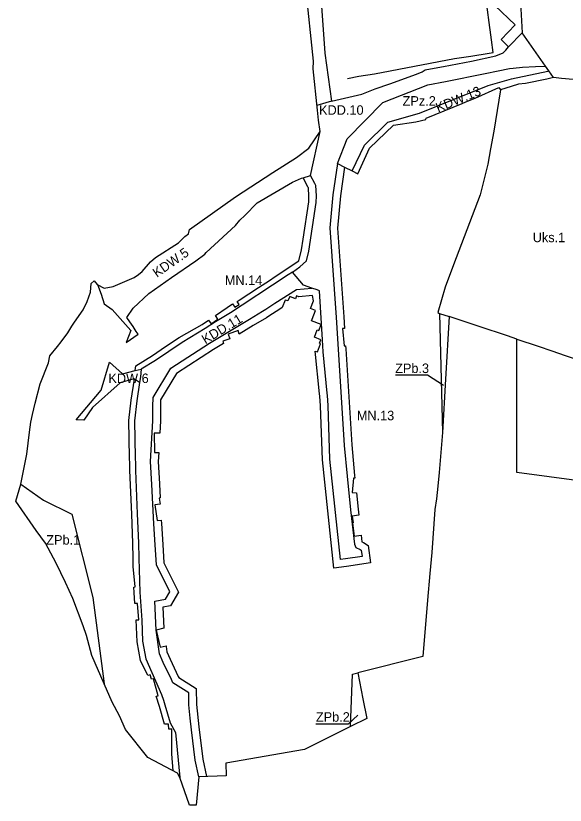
# Model space of a CAD drawing. Extents: x 7416797 to 7419013, y 5549660 to 5551534.
# Drawn here: x 7417073.2 to 7417362.3, y 5550025.1 to 5550440.3 of the extents above; entities that cross this region are included whole.
import ezdxf

# ---------------------------------------------------------------- set-up
doc = ezdxf.new("R2010")
doc.units = 0
for name, color, linetype in [('LIN_Linia Zabudowy Nieprzekraczalna', 7, 'Continuous'), ('LIN_linie_rozgraniczajace', 7, 'Continuous'), ('TXT_Oznaczenia_przeznaczen', 7, 'Continuous')]:
    doc.layers.add(name, color=color, linetype=linetype)

msp = doc.modelspace()

# ---------------------------------------------------------------- linework, layer by layer
at = {"layer": 'LIN_Linia Zabudowy Nieprzekraczalna'}
for points in [[(7417247.75, 5550407.37), (7417253.8, 5550408.44), (7417261.96, 5550409.76), (7417304.01, 5550417.81), (7417312.68, 5550419.07), (7417322.33, 5550420.71), (7417324.39, 5550421.04), (7417323.56, 5550427.64), (7417321.99, 5550439.43), (7417321.8, 5550440.84), (7417319.15, 5550460.7), (7417310.86, 5550470.5), (7417297.14, 5550487.32), (7417222.5, 5550577.57)], [(7417246.22, 5550360.69), (7417244.04, 5550345.66), (7417242.48, 5550328.66), (7417245.86, 5550281.92), (7417246.2, 5550275.84), (7417245.19, 5550275.76), (7417245.92, 5550266.61), (7417246.73, 5550266.68), (7417246.82, 5550265.17), (7417250.07, 5550214.57), (7417251.49, 5550198.49), (7417251.63, 5550197.06), (7417250.85, 5550197.11), (7417250.29, 5550189.57), (7417252.45, 5550189.39), (7417253.35, 5550180.78), (7417253.7, 5550177.66), (7417250.29, 5550177.07), (7417250.79, 5550173.66), (7417250.34, 5550173.6), (7417251.26, 5550166.59), (7417254.88, 5550167.19), (7417255.31, 5550163.58), (7417256.18, 5550163.2), (7417258.7, 5550161.72), (7417259.89, 5550152.58), (7417247.25, 5550150.7), (7417240.53, 5550149.72), (7417234.53, 5550206.76), (7417233.56, 5550235.14), (7417233.19, 5550240.22), (7417233.06, 5550241.43), (7417230.83, 5550263.92), (7417232.02, 5550263.48), (7417233.6, 5550267.82), (7417233.07, 5550268.07), (7417233.77, 5550269.92), (7417230.45, 5550271.2), (7417231.86, 5550275.07), (7417232.62, 5550274.76), (7417233.88, 5550277.84), (7417228.87, 5550279.8), (7417229.23, 5550280.74), (7417230.93, 5550285.35), (7417228.28, 5550286.37), (7417229.79, 5550290.41), (7417229.39, 5550293.12), (7417222.21, 5550292.41), (7417220.92, 5550292.92), (7417220.39, 5550291.47), (7417217.37, 5550292.57), (7417216.42, 5550290.29), (7417214.99, 5550290.79), (7417213.39, 5550286.81), (7417211.63, 5550285.69), (7417206.89, 5550282.58), (7417205.11, 5550281.48), (7417198.17, 5550277.37), (7417190.74, 5550272.9), (7417190.19, 5550274.69), (7417184.9, 5550272.8), (7417185.76, 5550270.34), (7417182.08, 5550269.11), (7417182.44, 5550267.9), (7417177.19, 5550264.75), (7417157.76, 5550252.08), (7417149.45, 5550238.3), (7417149.38, 5550234.69), (7417149.34, 5550232.65), (7417149.33, 5550227.2), (7417148.98, 5550220.68), (7417145.98, 5550220.69), (7417146.18, 5550210.55), (7417148.43, 5550210.57), (7417148.17, 5550205.77), (7417148.81, 5550194.16), (7417148.81, 5550193.96), (7417149.18, 5550186.7), (7417148.66, 5550186.62), (7417149.12, 5550183.4), (7417146.45, 5550183.1), (7417147.6, 5550174.79), (7417149.77, 5550175.07)], [(7417222.1, 5550311.42), (7417223.54, 5550317.23), (7417224.38, 5550322.78), (7417227.36, 5550342.44), (7417227.49, 5550345.47), (7417227.24, 5550349.72), (7417227.06, 5550349.99), (7417224.43, 5550355.11)], [(7417136.12, 5550253.72), (7417136.33, 5550256.25), (7417145.14, 5550261.56), (7417152.07, 5550266.3), (7417159.13, 5550271.11), (7417171.29, 5550277.95), (7417174.71, 5550280.24), (7417175.98, 5550278.34), (7417179.61, 5550280.78), (7417178.34, 5550282.67), (7417184.51, 5550286.81), (7417187.26, 5550288.78), (7417188.43, 5550286.94), (7417190.82, 5550288.46), (7417189.78, 5550290.08), (7417190.77, 5550290.71), (7417200.94, 5550297.43), (7417206.71, 5550301.14), (7417209.68, 5550303.12), (7417222.1, 5550311.42)], [(7417156, 5550043.16), (7417155.29, 5550052.07), (7417155.36, 5550065.12), (7417153.75, 5550065.09), (7417153.65, 5550067.74), (7417151.49, 5550067.68), (7417148.89, 5550077.06), (7417147.07, 5550082.35), (7417148.09, 5550082.62), (7417145.71, 5550091.56), (7417144.69, 5550091.28), (7417144.01, 5550093.69), (7417142.74, 5550093.31), (7417138.78, 5550101.2), (7417137.02, 5550111.03), (7417136.49, 5550122.54), (7417137.95, 5550122.62), (7417137.34, 5550131.24), (7417135.93, 5550131.14), (7417135.45, 5550136.89), (7417135.37, 5550139.83), (7417136.12, 5550139.91), (7417134.92, 5550150.71), (7417134.96, 5550154.93), (7417134.81, 5550162.92), (7417134.21, 5550178.14), (7417133.24, 5550201.1), (7417133.22, 5550204.45), (7417133.07, 5550207.93), (7417132.76, 5550227.34), (7417133.97, 5550238.13), (7417135.63, 5550249.12)], [(7417149.77, 5550175.07), (7417149.86, 5550173.23), (7417150.56, 5550162.21), (7417151.14, 5550152.5), (7417158.79, 5550137.12), (7417154.6, 5550129.95), (7417150.51, 5550129.15), (7417151.12, 5550118.17), (7417147, 5550117.15), (7417149.26, 5550108.2), (7417152.27, 5550108.97), (7417152.32, 5550108.61), (7417152.7, 5550105.77), (7417154.4, 5550101.84), (7417158.68, 5550092.84), (7417158.95, 5550092.28)], [(7417158.95, 5550092.28), (7417168.15, 5550086.46), (7417168.32, 5550078.1), (7417169.45, 5550066.24), (7417171.6, 5550049.37), (7417173.58, 5550040.2)]]:
    msp.add_lwpolyline(points, dxfattribs=at)
at = {"layer": 'LIN_linie_rozgraniczajace'}
for p, q in [((7417332.42, 5550424.03), (7417339.72, 5550431.23)), ((7417239.29, 5550395.46), (7417231.66, 5550393.13)), ((7417296.14, 5550283.77), (7417297.76, 5550221.07))]:
    msp.add_line(p, q, dxfattribs=at)
for points in [[(7417192.07, 5550542.59), (7417215.52, 5550524.38), (7417226.02, 5550511.19), (7417227.34, 5550506.79), (7417228.19, 5550503.17), (7417226.59, 5550485.84), (7417226.54, 5550483.39), (7417227.53, 5550475.07), (7417228.5, 5550472.11), (7417230.95, 5550473.36), (7417232.07, 5550469.35), (7417229.43, 5550467.65), (7417233.13, 5550457.84), (7417235.85, 5550420.62), (7417239.29, 5550395.46)], [(7417326.46, 5550467.59), (7417325.31, 5550460.13), (7417326.01, 5550460.16), (7417325.83, 5550454.74), (7417325.27, 5550453.92), (7417325.23, 5550445.71), (7417335.92, 5550435.5), (7417328.63, 5550427.84), (7417332.42, 5550424.03)], [(7417326.46, 5550467.59), (7417328.63, 5550465.05), (7417335.93, 5550455.83), (7417338.71, 5550447.06), (7417339.72, 5550431.23)], [(7417390.48, 5550192.96), (7417336.94, 5550200.05), (7417336.94, 5550270.27), (7417331.92, 5550271.93), (7417317.1, 5550276.78), (7417301.18, 5550282.09), (7417299.33, 5550249.13), (7417297.76, 5550221.07), (7417296.01, 5550199.99), (7417295.28, 5550192.83), (7417294.66, 5550186.18), (7417293.71, 5550180.54), (7417292.06, 5550157.96), (7417291.12, 5550147.03), (7417289.91, 5550132.95), (7417287.42, 5550103.21), (7417253.22, 5550094.63), (7417253.22, 5550094.63), (7417255.88, 5550081.06), (7417257.96, 5550070.68), (7417249.41, 5550066.42), (7417225.06, 5550054.3), (7417183.72, 5550047.24), (7417183.92, 5550040.58), (7417169.53, 5550040.05), (7417168.2, 5550025.1), (7417164.63, 5550025.07), (7417159.58, 5550039.59), (7417158.34, 5550041.93), (7417142.67, 5550050.15), (7417130.98, 5550064.94), (7417127.85, 5550072.02), (7417123.85, 5550079.26), (7417119.8, 5550088.9), (7417113.19, 5550103.9), (7417110.37, 5550114.34), (7417108.61, 5550119.37), (7417103.27, 5550133.87), (7417099.38, 5550142.22), (7417094.51, 5550152.38), (7417088.83, 5550162.86), (7417084, 5550169.62), (7417073.22, 5550184.99), (7417075.91, 5550193.91), (7417079.08, 5550209.65), (7417080.36, 5550221.26), (7417081.19, 5550226.55), (7417081.98, 5550230.63), (7417083.46, 5550236.6), (7417085.98, 5550246.76), (7417090.38, 5550257.79), (7417091.19, 5550261.38), (7417095.09, 5550266.34), (7417097.05, 5550268.72), (7417100.56, 5550273.47), (7417102.78, 5550276.97), (7417104.18, 5550279.17), (7417108.62, 5550285.65), (7417110.84, 5550290.05), (7417112.49, 5550294.97), (7417112.86, 5550299.39), (7417114.5, 5550300.96), (7417116.08, 5550299.02), (7417119.81, 5550297.07), (7417124.53, 5550297.96), (7417135.55, 5550302.66), (7417137.79, 5550304.2), (7417139.67, 5550305.83), (7417144.13, 5550310.81), (7417146.78, 5550313.12), (7417158.78, 5550320.87), (7417162.2, 5550324.16), (7417164.09, 5550325.68), (7417164.65, 5550327.91), (7417188.77, 5550345.1), (7417208.42, 5550357.91), (7417221.01, 5550365.77), (7417227.42, 5550370.64), (7417233.31, 5550379.43), (7417232.56, 5550385.38), (7417231.91, 5550390.59), (7417229.78, 5550412.37), (7417229.81, 5550416.47), (7417225.79, 5550455.14)], [(7417351.92, 5550413.77), (7417339.72, 5550431.23)], [(7417239.29, 5550395.46), (7417255.29, 5550399.08), (7417262.39, 5550401.86), (7417270.09, 5550404.43), (7417284.04, 5550409.65), (7417287.08, 5550410.85), (7417288.62, 5550411.87), (7417295.26, 5550413.07), (7417298.21, 5550413.64), (7417313.04, 5550416.48), (7417325.75, 5550419.14), (7417329.64, 5550420.83), (7417331.13, 5550422.13), (7417332.42, 5550424.03)], [(7417242.45, 5550362.59), (7417247.56, 5550375.64), (7417266.42, 5550394.7), (7417289.99, 5550403.9), (7417299.31, 5550405.73), (7417320.12, 5550409.89), (7417326.99, 5550411.28), (7417332.96, 5550412.55), (7417334.96, 5550412.72), (7417339.8, 5550413.26), (7417346.72, 5550413.62), (7417351.92, 5550413.77)], [(7417353.63, 5550411.33), (7417351.92, 5550413.77)], [(7417250.21, 5550358.67), (7417256.73, 5550372.3), (7417269, 5550384.37), (7417285.61, 5550389.11), (7417303.08, 5550396.02), (7417321.69, 5550403.67), (7417334.07, 5550407.09), (7417353.12, 5550411.22), (7417353.63, 5550411.33)], [(7417356.11, 5550407.77), (7417353.63, 5550411.33)], [(7417356.11, 5550407.77), (7417352.61, 5550406.96), (7417341.37, 5550404.74), (7417337.76, 5550404.24), (7417333.79, 5550403.02), (7417328.24, 5550401.29)], [(7417408.78, 5550369.31), (7417405.88, 5550372.98), (7417391.88, 5550393.26), (7417388.87, 5550397.33), (7417387.65, 5550399.03), (7417383.74, 5550404.65), (7417372.6, 5550406.27), (7417360.36, 5550407.34), (7417356.11, 5550407.77)], [(7417242.45, 5550362.59), (7417246.22, 5550360.69), (7417250.21, 5550358.67), (7417253.18, 5550357.17), (7417259.35, 5550370.61), (7417271.88, 5550382.78), (7417283.74, 5550384.58), (7417289, 5550385.75), (7417289.17, 5550386.4), (7417308.05, 5550394.22), (7417310.03, 5550395.04), (7417314.85, 5550397.03), (7417327.33, 5550402.65), (7417328.24, 5550401.29)], [(7417328.24, 5550401.29), (7417326.44, 5550390.47), (7417324.73, 5550379.59), (7417322.92, 5550370.32), (7417321.52, 5550362.27), (7417317.57, 5550346.09), (7417313.37, 5550334.99), (7417303.62, 5550309.22), (7417299.22, 5550297.58), (7417295.21, 5550284.14), (7417296.14, 5550283.77)], [(7417228.32, 5550356.29), (7417233.31, 5550379.43)], [(7417336.94, 5550270.27), (7417348.08, 5550266.58), (7417355.33, 5550263.98), (7417362.32, 5550261.63), (7417385.88, 5550253.92), (7417397.94, 5550250.05), (7417400.58, 5550263.54), (7417401.84, 5550273.38), (7417402.48, 5550277.5), (7417403.1, 5550282.66), (7417404.5, 5550295.46), (7417404.9, 5550299.68), (7417405.3, 5550310), (7417405.5, 5550314.62), (7417406.24, 5550325.37), (7417406.27, 5550328.97), (7417406.52, 5550333.54), (7417406.79, 5550337.31), (7417407.4, 5550350.15), (7417407.79, 5550358), (7417408.02, 5550362.03), (7417408.15, 5550364.55), (7417408.17, 5550365.02), (7417408.78, 5550369.31)], [(7417242.45, 5550362.59), (7417240.07, 5550346.13), (7417238.47, 5550328.7), (7417241.87, 5550281.66), (7417242.82, 5550264.93), (7417246.09, 5550214.26), (7417247.51, 5550198.1), (7417249.37, 5550180.35), (7417251.42, 5550162.36), (7417252.1, 5550160.61), (7417254.36, 5550159.63), (7417254.99, 5550159.26), (7417255.42, 5550155.96), (7417246.67, 5550154.66), (7417244.07, 5550154.28), (7417238.52, 5550207.04), (7417237.55, 5550235.35), (7417237.17, 5550240.57), (7417237.04, 5550241.83), (7417234.88, 5550263.6), (7417234.67, 5550269.85), (7417233.11, 5550295.66), (7417231.85, 5550296.06), (7417229, 5550297.1)], [(7417116.21, 5550298.95), (7417118.18, 5550293.92), (7417119.75, 5550288.86), (7417124.02, 5550285.82), (7417133.75, 5550274.81), (7417131.33, 5550268.51), (7417137.53, 5550272.87), (7417136.57, 5550274.31), (7417134.94, 5550276.86), (7417133.28, 5550279.26), (7417131.73, 5550281.55), (7417134.95, 5550286.52), (7417143.2, 5550294.26), (7417155.07, 5550302.6), (7417168.02, 5550311.43), (7417172.69, 5550314.82), (7417173.45, 5550315.81), (7417188.78, 5550330.04), (7417191.12, 5550332.84), (7417193.82, 5550335.25), (7417200.26, 5550341.86), (7417218.77, 5550352.69), (7417223.56, 5550354.84), (7417224.43, 5550355.11), (7417228.32, 5550356.29)], [(7417218.76, 5550305.52), (7417222.73, 5550308.29), (7417226.21, 5550311.39), (7417227.47, 5550316.45), (7417231.34, 5550342.05), (7417231.49, 5550345.5), (7417231.17, 5550351.02), (7417230.52, 5550352.01), (7417228.32, 5550356.29)], [(7417218.76, 5550305.52), (7417216.54, 5550303.96), (7417208.34, 5550298.66), (7417192.37, 5550288), (7417186.23, 5550284.1), (7417178.33, 5550279.28), (7417172.83, 5550275.82), (7417160.72, 5550268.48), (7417146.73, 5550259.06), (7417139.16, 5550254.49)], [(7417229, 5550297.1), (7417224.65, 5550298.68), (7417218.76, 5550305.52)], [(7417169.53, 5550040.05), (7417167.65, 5550048.69), (7417165.62, 5550064.74), (7417164.97, 5550070.82), (7417164.32, 5550077.88), (7417164.19, 5550084.23), (7417155.86, 5550089.5), (7417155.07, 5550091.11), (7417150.76, 5550100.19), (7417148.81, 5550104.69), (7417147, 5550117.15), (7417146.33, 5550132.41), (7417152.06, 5550133.53), (7417154.25, 5550137.27), (7417147.2, 5550151.45), (7417146.57, 5550161.96), (7417145.87, 5550173), (7417144.82, 5550193.75), (7417144.17, 5550205.77), (7417145.33, 5550227.31), (7417145.34, 5550232.69), (7417145.38, 5550234.77), (7417145.47, 5550239.45), (7417154.81, 5550254.93), (7417175.07, 5550268.14), (7417196.12, 5550280.8), (7417203.04, 5550284.9), (7417204.74, 5550285.95), (7417209.46, 5550289.05), (7417220.89, 5550296.3), (7417229, 5550297.1)], [(7417296.14, 5550283.77), (7417301.18, 5550282.09)], [(7417138.37, 5550247.43), (7417135.63, 5550249.12), (7417135.3, 5550249.32), (7417128.06, 5550247.23), (7417113.6, 5550234.32), (7417108.98, 5550227.52), (7417104.96, 5550227.71), (7417118.14, 5550243.31), (7417122.58, 5550258.1), (7417129.44, 5550252.03), (7417136.12, 5550253.72), (7417139.16, 5550254.49)], [(7417139.16, 5550254.49), (7417138.81, 5550250.33), (7417138.37, 5550247.43)], [(7417138.37, 5550247.43), (7417136.91, 5550237.74), (7417135.73, 5550227.2), (7417136.03, 5550208.02), (7417136.18, 5550204.52), (7417136.2, 5550201.17), (7417137.17, 5550178.26), (7417137.77, 5550163.01), (7417137.92, 5550155), (7417138.41, 5550137.04), (7417139.51, 5550122.41), (7417139.97, 5550111.36), (7417141.64, 5550102.07), (7417149.89, 5550083.26), (7417150.96, 5550080.28), (7417151.72, 5550077.94), (7417154.37, 5550068.39), (7417157.33, 5550063.24), (7417159.58, 5550039.59)], [(7417075.91, 5550193.91), (7417087.82, 5550185.53), (7417102.8, 5550178.11), (7417113.75, 5550134.39), (7417119.8, 5550088.9)], [(7417249.41, 5550066.42), (7417250.35, 5550093.91), (7417253.22, 5550094.63)]]:
    msp.add_lwpolyline(points, dxfattribs=at)
at = {"layer": 'TXT_Oznaczenia_przeznaczen'}
for points in [[(7417298.28, 5550245.82), (7417289.86, 5550251.32), (7417272.95, 5550251.32)], [(7417253.13, 5550072.49), (7417248.09, 5550067.73), (7417231.14, 5550067.73)]]:
    msp.add_lwpolyline(points, dxfattribs=at)

# ---------------------------------------------------------------- texts
for s, rotation, p in [('KDW.13', 22.3181, (7417295.44, 5550389.37)), ('KDW.5', 34.9748, (7417147.47, 5550302.44)), ('KDD.11', 31.0497, (7417172.96, 5550267.42))]:
    msp.add_text(s, height=5, rotation=rotation, dxfattribs=at).set_placement(p)
for s, p in [('ZPz.2', (7417276.77, 5550393.02)), ('KDD.10', (7417232.81, 5550388.22)), ('Uks.1', (7417345.23, 5550321.21)), ('MN.14', (7417183.21, 5550298.7)), ('ZPb.3', (7417272.83, 5550252.38)), ('KDW.6', (7417121.98, 5550247.11)), ('MN.13', (7417252.66, 5550227.53)), ('ZPb.1', (7417089.28, 5550162.13)), ('ZPb.2', (7417231.14, 5550068.98))]:
    msp.add_text(s, height=5, dxfattribs=at).set_placement(p)

doc.saveas('drawing.dxf')
